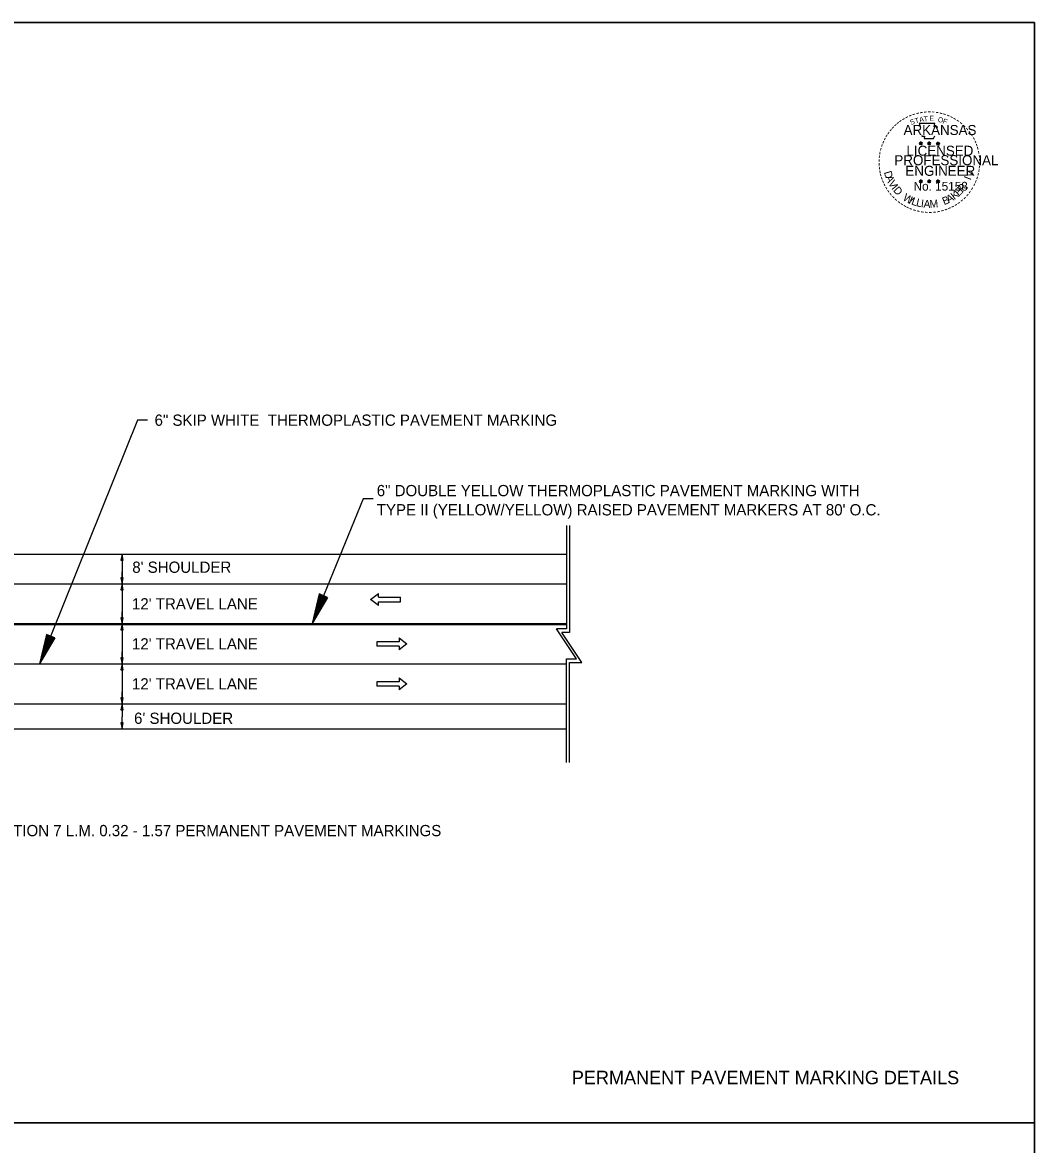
# Model space of a CAD drawing. Extents: x 1373096 to 1373266, y 381130 to 381790.
# Drawn here: x 1373164.8 to 1373266, y 381568 to 381680.2 of the extents above; entities that cross this region are included whole.
import ezdxf

# ---------------------------------------------------------------- set-up
doc = ezdxf.new("R2010")
doc.units = 0
for name, color, linetype in [('Default', 7, 'Continuous'), ('DSN_DRFT_Junk-No-Plot', 7, 'Continuous'), ('R_Border Notes', 7, 'Continuous'), ('R_Border PE', 7, 'Continuous'), ('R_Draft', 7, 'Continuous')]:
    doc.layers.add(name, color=color, linetype=linetype)

msp = doc.modelspace()

# ---------------------------------------------------------------- linework, layer by layer
at = {"layer": 'Default'}
for p, q in [((1373176.29, 381640.41), (1373166.5, 381616.04)), ((1373177.29, 381640.41), (1373176.29, 381640.41)), ((1373198.85, 381632.56), (1373193.75, 381620.09)), ((1373199.85, 381632.56), (1373198.85, 381632.56)), ((1373219.17, 381629.87), (1373219.17, 381619.54)), ((1373219.5, 381629.87), (1373219.5, 381619.2)), ((1373194.46, 381623.04), (1373193.75, 381620.09)), ((1373195.29, 381622.7), (1373193.75, 381620.09)), ((1373194.53, 381623.01), (1373193.94, 381620.55)), ((1373195.22, 381622.73), (1373193.94, 381620.55)), ((1373194.6, 381622.98), (1373194.13, 381621.03)), ((1373195.15, 381622.76), (1373194.13, 381621.03)), ((1373194.67, 381622.96), (1373194.32, 381621.5)), ((1373195.08, 381622.79), (1373194.32, 381621.5)), ((1373195.29, 381622.7), (1373194.46, 381623.04)), ((1373194.74, 381622.93), (1373194.51, 381621.97)), ((1373195.01, 381622.82), (1373194.51, 381621.97)), ((1373194.81, 381622.9), (1373194.7, 381622.43)), ((1373194.94, 381622.85), (1373194.7, 381622.43)), ((1373199.6, 381622.49), (1373200.38, 381623.09)), ((1373200.38, 381621.89), (1373199.6, 381622.49)), ((1373200.38, 381622.71), (1373200.38, 381623.09)), ((1373200.38, 381622.71), (1373202.58, 381622.71)), ((1373202.58, 381622.26), (1373202.58, 381622.71)), ((1373200.38, 381622.26), (1373202.58, 381622.26)), ((1373200.38, 381621.89), (1373200.38, 381622.26)), ((1373219.17, 381619.54), (1373218.17, 381619.54)), ((1373220.17, 381616.54), (1373218.17, 381619.54)), ((1373220.72, 381616.2), (1373218.72, 381619.2)), ((1373219.5, 381619.2), (1373218.72, 381619.2)), ((1373167.2, 381618.99), (1373166.5, 381616.04)), ((1373168.04, 381618.65), (1373166.5, 381616.04)), ((1373167.27, 381618.96), (1373166.69, 381616.5)), ((1373167.97, 381618.68), (1373166.69, 381616.5)), ((1373167.34, 381618.93), (1373166.88, 381616.98)), ((1373167.9, 381618.71), (1373166.88, 381616.98)), ((1373167.41, 381618.9), (1373167.07, 381617.44)), ((1373167.83, 381618.74), (1373167.07, 381617.44)), ((1373168.04, 381618.65), (1373167.2, 381618.99)), ((1373167.48, 381618.88), (1373167.26, 381617.92)), ((1373167.75, 381618.77), (1373167.26, 381617.92)), ((1373167.55, 381618.85), (1373167.44, 381618.38)), ((1373167.68, 381618.79), (1373167.44, 381618.38)), ((1373202.45, 381618.26), (1373200.24, 381618.26)), ((1373200.24, 381618.26), (1373200.24, 381617.81)), ((1373202.45, 381618.64), (1373202.45, 381618.26)), ((1373202.45, 381618.64), (1373203.23, 381618.04)), ((1373203.23, 381618.04), (1373202.45, 381617.44)), ((1373202.45, 381617.81), (1373200.24, 381617.81)), ((1373202.45, 381617.81), (1373202.45, 381617.44)), ((1373219.17, 381606.2), (1373219.17, 381616.54)), ((1373219.17, 381616.54), (1373220.17, 381616.54)), ((1373219.5, 381606.2), (1373219.5, 381616.2)), ((1373219.5, 381616.2), (1373220.72, 381616.2)), ((1373202.45, 381614.64), (1373202.45, 381614.26)), ((1373202.45, 381614.64), (1373203.23, 381614.04)), ((1373202.45, 381614.26), (1373200.24, 381614.26)), ((1373200.24, 381614.26), (1373200.24, 381613.81)), ((1373202.45, 381613.81), (1373200.24, 381613.81)), ((1373203.23, 381614.04), (1373202.45, 381613.44)), ((1373202.45, 381613.81), (1373202.45, 381613.44))]:
    msp.add_line(p, q, dxfattribs=at)
for points in [[(1373095.97, 381680.17), (1373095.97, 381570.17), (1373265.97, 381570.17), (1373265.97, 381680.17)], [(1373095.97, 381680.17), (1373095.97, 381570.17), (1373265.97, 381570.17), (1373265.97, 381680.17)], [(1373095.97, 381570.17), (1373095.97, 381460.17), (1373265.97, 381460.17), (1373265.97, 381570.17)]]:
    msp.add_lwpolyline(points, close=True, dxfattribs=at)
at = {"layer": 'DSN_DRFT_Junk-No-Plot'}
msp.add_line((1373174.76, 381625.81), (1373174.76, 381610.74), dxfattribs=at)
for points in [[(1373095.97, 381680.17), (1373265.97, 381680.17), (1373265.97, 381570.17), (1373095.97, 381570.17)], [(1373095.97, 381680.17), (1373095.97, 381570.17), (1373265.97, 381570.17), (1373265.97, 381680.17)], [(1373095.97, 381570.17), (1373265.97, 381570.17), (1373265.97, 381460.17), (1373095.97, 381460.17)], [(1373095.97, 381570.17), (1373095.97, 381460.17), (1373265.97, 381460.17), (1373265.97, 381570.17)]]:
    msp.add_lwpolyline(points, close=True, dxfattribs=at)
for points in [[(1373174.76, 381627.01), (1373174.64, 381626.41), (1373174.88, 381626.41), (1373174.76, 381627.01), (1373174.76, 381625.81)], [(1373174.76, 381624.04), (1373174.88, 381624.64), (1373174.64, 381624.64), (1373174.76, 381624.04), (1373174.76, 381625.24)], [(1373174.76, 381624.04), (1373174.88, 381624.64), (1373174.64, 381624.64), (1373174.76, 381624.04), (1373174.76, 381625.24)], [(1373174.76, 381624.04), (1373174.64, 381623.44), (1373174.88, 381623.44), (1373174.76, 381624.04), (1373174.76, 381622.84)], [(1373174.76, 381620.04), (1373174.88, 381620.64), (1373174.64, 381620.64), (1373174.76, 381620.04), (1373174.76, 381621.24)], [(1373174.76, 381620.04), (1373174.64, 381619.44), (1373174.88, 381619.44), (1373174.76, 381620.04), (1373174.76, 381618.84)], [(1373174.76, 381616.04), (1373174.88, 381616.64), (1373174.64, 381616.64), (1373174.76, 381616.04), (1373174.76, 381617.24)], [(1373174.76, 381616.04), (1373174.64, 381615.44), (1373174.88, 381615.44), (1373174.76, 381616.04), (1373174.76, 381614.84)], [(1373174.76, 381612.04), (1373174.88, 381612.64), (1373174.64, 381612.64), (1373174.76, 381612.04), (1373174.76, 381613.24)], [(1373174.76, 381612.04), (1373174.64, 381611.44), (1373174.88, 381611.44), (1373174.76, 381612.04), (1373174.76, 381610.84)], [(1373174.76, 381609.54), (1373174.88, 381610.14), (1373174.64, 381610.14), (1373174.76, 381609.54), (1373174.76, 381610.74)]]:
    msp.add_lwpolyline(points, dxfattribs=at)
at = {"layer": 'R_Border PE'}
for p, q in [((1373254.43, 381668.13), (1373254.6, 381668.07)), ((1373254.43, 381668.13), (1373254.56, 381668.11)), ((1373254.43, 381668.13), (1373254.55, 381668.07)), ((1373254.5, 381667.93), (1373254.6, 381668.07)), ((1373254.5, 381667.93), (1373254.56, 381668.05)), ((1373254.5, 381667.93), (1373254.6, 381668.03)), ((1373254.6, 381668.26), (1373254.58, 381668.13)), ((1373254.6, 381668.07), (1373254.6, 381668.26)), ((1373254.6, 381668.26), (1373254.63, 381668.13)), ((1373254.78, 381668.13), (1373254.6, 381668.07)), ((1373254.71, 381667.93), (1373254.6, 381668.07)), ((1373254.71, 381667.93), (1373254.6, 381668.03)), ((1373254.78, 381668.13), (1373254.63, 381668.11)), ((1373254.71, 381667.93), (1373254.64, 381668.07)), ((1373254.78, 381668.13), (1373254.67, 381668.08)), ((1373255.26, 381668.13), (1373255.44, 381668.07)), ((1373255.26, 381668.13), (1373255.39, 381668.11)), ((1373255.26, 381668.13), (1373255.38, 381668.07)), ((1373255.33, 381667.93), (1373255.44, 381668.07)), ((1373255.33, 381667.93), (1373255.39, 381668.05)), ((1373255.33, 381667.93), (1373255.44, 381668.03)), ((1373255.44, 381668.26), (1373255.42, 381668.13)), ((1373255.44, 381668.07), (1373255.44, 381668.26)), ((1373255.44, 381668.26), (1373255.46, 381668.13)), ((1373255.61, 381668.13), (1373255.44, 381668.07)), ((1373255.54, 381667.93), (1373255.44, 381668.07)), ((1373255.54, 381667.93), (1373255.44, 381668.03)), ((1373255.61, 381668.13), (1373255.47, 381668.11)), ((1373255.54, 381667.93), (1373255.48, 381668.07)), ((1373255.61, 381668.13), (1373255.51, 381668.08)), ((1373256.15, 381668.12), (1373256.32, 381668.07)), ((1373256.15, 381668.12), (1373256.27, 381668.1)), ((1373256.15, 381668.12), (1373256.26, 381668.06)), ((1373256.21, 381667.92), (1373256.32, 381668.07)), ((1373256.21, 381667.92), (1373256.28, 381668.04)), ((1373256.21, 381667.92), (1373256.32, 381668.03)), ((1373256.32, 381668.25), (1373256.3, 381668.12)), ((1373256.32, 381668.07), (1373256.32, 381668.25)), ((1373256.32, 381668.25), (1373256.34, 381668.13)), ((1373256.49, 381668.12), (1373256.32, 381668.07)), ((1373256.43, 381667.92), (1373256.32, 381668.07)), ((1373256.43, 381667.92), (1373256.32, 381668.03)), ((1373256.49, 381668.12), (1373256.35, 381668.1)), ((1373256.43, 381667.92), (1373256.36, 381668.07)), ((1373256.49, 381668.12), (1373256.39, 381668.07)), ((1373254.43, 381664.34), (1373254.6, 381664.29)), ((1373254.43, 381664.34), (1373254.55, 381664.32)), ((1373254.43, 381664.34), (1373254.55, 381664.28)), ((1373254.49, 381664.14), (1373254.6, 381664.29)), ((1373254.49, 381664.14), (1373254.56, 381664.26)), ((1373254.49, 381664.14), (1373254.6, 381664.25)), ((1373254.6, 381664.47), (1373254.58, 381664.34)), ((1373254.6, 381664.29), (1373254.6, 381664.47)), ((1373254.6, 381664.47), (1373254.63, 381664.35)), ((1373254.77, 381664.34), (1373254.6, 381664.29)), ((1373254.71, 381664.14), (1373254.6, 381664.29)), ((1373254.71, 381664.14), (1373254.6, 381664.25)), ((1373254.77, 381664.34), (1373254.63, 381664.32)), ((1373254.71, 381664.14), (1373254.64, 381664.28)), ((1373254.77, 381664.34), (1373254.67, 381664.29)), ((1373255.26, 381664.34), (1373255.44, 381664.29)), ((1373255.26, 381664.34), (1373255.39, 381664.32)), ((1373255.26, 381664.34), (1373255.38, 381664.28)), ((1373255.33, 381664.14), (1373255.44, 381664.29)), ((1373255.33, 381664.14), (1373255.39, 381664.26)), ((1373255.33, 381664.14), (1373255.43, 381664.25)), ((1373255.44, 381664.47), (1373255.42, 381664.34)), ((1373255.54, 381664.14), (1373255.43, 381664.25)), ((1373255.44, 381664.29), (1373255.44, 381664.47)), ((1373255.44, 381664.47), (1373255.46, 381664.35)), ((1373255.61, 381664.34), (1373255.44, 381664.29)), ((1373255.54, 381664.14), (1373255.44, 381664.29)), ((1373255.61, 381664.34), (1373255.47, 381664.32)), ((1373255.54, 381664.14), (1373255.47, 381664.28)), ((1373255.61, 381664.34), (1373255.51, 381664.29)), ((1373256.14, 381664.34), (1373256.32, 381664.28)), ((1373256.14, 381664.34), (1373256.27, 381664.32)), ((1373256.14, 381664.34), (1373256.26, 381664.28)), ((1373256.21, 381664.13), (1373256.32, 381664.28)), ((1373256.21, 381664.13), (1373256.27, 381664.26)), ((1373256.21, 381664.13), (1373256.32, 381664.24)), ((1373256.32, 381664.47), (1373256.3, 381664.34)), ((1373256.32, 381664.28), (1373256.32, 381664.47)), ((1373256.32, 381664.47), (1373256.34, 381664.34)), ((1373256.49, 381664.34), (1373256.32, 381664.28)), ((1373256.43, 381664.13), (1373256.32, 381664.28)), ((1373256.43, 381664.13), (1373256.32, 381664.24)), ((1373256.49, 381664.34), (1373256.35, 381664.31)), ((1373256.43, 381664.13), (1373256.36, 381664.28)), ((1373256.49, 381664.34), (1373256.39, 381664.29))]:
    msp.add_line(p, q, dxfattribs=at)
for points in [[(1373254.45, 381670.07), (1373254.58, 381669.66)], [(1373256.2, 381669.61), (1373256.28, 381669.75), (1373255.93, 381669.74), (1373256.01, 381670.07), (1373254.45, 381670.07)], [(1373254.7, 381668.86), (1373254.7, 381668.81), (1373254.98, 381668.8), (1373254.95, 381668.57), (1373255.88, 381668.57), (1373255.99, 381668.84)], [(1373254.6, 381668.26), (1373254.71, 381667.93), (1373254.43, 381668.13), (1373254.78, 381668.13), (1373254.5, 381667.93), (1373254.6, 381668.26)], [(1373255.44, 381668.26), (1373255.54, 381667.93), (1373255.26, 381668.13), (1373255.61, 381668.13), (1373255.33, 381667.93), (1373255.44, 381668.26)], [(1373256.32, 381668.25), (1373256.43, 381667.92), (1373256.15, 381668.12), (1373256.49, 381668.12), (1373256.21, 381667.92), (1373256.32, 381668.25)], [(1373254.6, 381664.47), (1373254.71, 381664.14), (1373254.43, 381664.34), (1373254.77, 381664.34), (1373254.49, 381664.14), (1373254.6, 381664.47)], [(1373255.44, 381664.47), (1373255.54, 381664.14), (1373255.26, 381664.34), (1373255.61, 381664.34), (1373255.33, 381664.14), (1373255.44, 381664.47)], [(1373256.32, 381664.47), (1373256.43, 381664.13), (1373256.14, 381664.34), (1373256.49, 381664.34), (1373256.21, 381664.13), (1373256.32, 381664.47)]]:
    msp.add_lwpolyline(points, dxfattribs=at)
for centre, radius in [((1373254.6, 381668.07), 0.0861), ((1373254.6, 381668.07), 0.0723), ((1373254.6, 381668.07), 0.0579), ((1373254.6, 381668.07), 0.0495), ((1373254.6, 381668.07), 0.0374), ((1373254.6, 381668.07), 0.0248), ((1373254.6, 381668.07), 0.0148), ((1373255.44, 381668.07), 0.0861), ((1373255.44, 381668.07), 0.0723), ((1373255.44, 381668.07), 0.0579), ((1373255.44, 381668.07), 0.0495), ((1373255.44, 381668.07), 0.0374), ((1373255.44, 381668.07), 0.0248), ((1373255.44, 381668.07), 0.0148), ((1373256.32, 381668.07), 0.0861), ((1373256.32, 381668.07), 0.0723), ((1373256.32, 381668.07), 0.0579), ((1373256.32, 381668.07), 0.0495), ((1373256.32, 381668.07), 0.0374), ((1373256.32, 381668.07), 0.0248), ((1373256.32, 381668.07), 0.0148), ((1373254.6, 381664.29), 0.0861), ((1373254.6, 381664.29), 0.0723), ((1373254.6, 381664.29), 0.0579), ((1373254.6, 381664.29), 0.0495), ((1373254.6, 381664.29), 0.0374), ((1373254.6, 381664.29), 0.0248), ((1373254.6, 381664.29), 0.0148), ((1373255.44, 381664.29), 0.0861), ((1373255.44, 381664.29), 0.0723), ((1373255.44, 381664.29), 0.0579), ((1373255.44, 381664.29), 0.0495), ((1373255.44, 381664.29), 0.0374), ((1373255.44, 381664.29), 0.0248), ((1373255.44, 381664.29), 0.0148), ((1373256.32, 381664.28), 0.0861), ((1373256.32, 381664.28), 0.0723), ((1373256.32, 381664.28), 0.0579), ((1373256.32, 381664.28), 0.0495), ((1373256.32, 381664.28), 0.0374), ((1373256.32, 381664.28), 0.0248), ((1373256.32, 381664.28), 0.0148)]:
    msp.add_circle(centre, radius, dxfattribs=at)
at = {"layer": 'R_Draft'}
for p, q in [((1373142.77, 381627.01), (1373219.16, 381627.01)), ((1373142.78, 381624.04), (1373219.17, 381624.04)), ((1373142.78, 381624.04), (1373219.17, 381624.04)), ((1373142.74, 381620.09), (1373219.14, 381620.09)), ((1373142.81, 381619.99), (1373219.2, 381619.99)), ((1373142.78, 381616.04), (1373219.17, 381616.04)), ((1373142.78, 381612.04), (1373219.17, 381612.04)), ((1373142.74, 381609.54), (1373219.13, 381609.54))]:
    msp.add_line(p, q, dxfattribs=at)

# ---------------------------------------------------------------- texts
at = {"layer": 'Default'}
for s, p in [('6" SKIP WHITE  THERMOPLASTIC PAVEMENT MARKING', (1373178.01, 381639.85)), ('6" DOUBLE YELLOW THERMOPLASTIC PAVEMENT MARKING WITH ', (1373200.22, 381632.81)), ("TYPE II (YELLOW/YELLOW) RAISED PAVEMENT MARKERS AT 80' O.C.", (1373200.22, 381630.89)), ("8' SHOULDER", (1373175.78, 381625.15)), ("12' TRAVEL LANE", (1373175.75, 381621.49)), ("12' TRAVEL LANE", (1373175.75, 381617.49)), ("12' TRAVEL LANE", (1373175.75, 381613.49)), ("6' SHOULDER", (1373175.96, 381610.05))]:
    msp.add_text(s, height=1.125, dxfattribs=at).set_placement(p)
at = {"layer": 'R_Border Notes'}
msp.add_text('PERMANENT PAVEMENT MARKING DETAILS', height=1.35, dxfattribs=at).set_placement((1373219.72, 381574.02))
at = {"layer": 'R_Border PE'}
for s, height, rotation, p in [('-', 0.8, 28.7918, (1373253.19, 381670.34)), ('-', 0.8, 24.3072, (1373253.51, 381670.5)), ('-', 0.8, 19.1761, (1373253.82, 381670.63)), ('T', 0.5, 16.4036, (1373254.08, 381670.07)), ('-', 0.8, 13.6302, (1373254.2, 381670.75)), ('A', 0.5, 11.2132, (1373254.5, 381670.2)), ('-', 0.8, 10.2193, (1373254.54, 381670.83)), ('T', 0.5, 6.0228, (1373254.92, 381670.28)), ('-', 0.8, 5.8968, (1373254.9, 381670.89)), ('-', 0.8, 0.1862, (1373255.29, 381670.92)), ('E', 0.5, 0.8323, (1373255.47, 381670.34)), ('-', 0.8, 357.743, (1373255.65, 381670.92)), ('-', 0.8, 352.1617, (1373256.02, 381670.89)), ('O', 0.5, 350.4515, (1373256.28, 381670.23)), ('-', 0.8, 347.2049, (1373256.38, 381670.83)), ('-', 0.8, 342.3362, (1373256.7, 381670.76)), ('-', 0.8, 337.8551, (1373257.07, 381670.64)), ('-', 0.8, 334.1211, (1373257.38, 381670.51)), ('-', 0.8, 329.6409, (1373257.67, 381670.37)), ('-', 0.8, 50.6142, (1373251.72, 381669.08)), ('-', 0.8, 48.4231, (1373251.92, 381669.32)), ('-', 0.8, 42.9622, (1373252.15, 381669.56)), ('-', 0.8, 38.9507, (1373252.36, 381669.77)), ('-', 0.8, 36.2317, (1373252.6, 381669.96)), ('-', 0.8, 34.0636, (1373252.89, 381670.15)), ('S', 0.5, 21.594, (1373253.63, 381669.91)), ('F', 0.5, 340.0707, (1373256.75, 381670.12)), ('-', 0.8, 325.8627, (1373257.99, 381670.19)), ('-', 0.8, 320.5297, (1373258.3, 381669.97)), ('-', 0.8, 315.5786, (1373258.6, 381669.73)), ('-', 0.8, 309.8797, (1373258.88, 381669.45)), ('-', 0.8, 62.8713, (1373251.2, 381668.22)), ('-', 0.8, 58.0706, (1373251.35, 381668.53)), ('-', 0.8, 54.2325, (1373251.52, 381668.79)), ('-', 0.8, 306.6522, (1373259.14, 381669.15)), ('-', 0.7, 303.6753, (1373259.39, 381668.87)), ('-', 0.8, 299.6684, (1373259.55, 381668.57)), ('-', 0.8, 75.461, (1373250.86, 381667.25)), ('-', 0.8, 72.3945, (1373250.96, 381667.6)), ('-', 0.8, 67.7743, (1373251.07, 381667.92)), ('-', 0.8, 294.6628, (1373259.71, 381668.26)), ('-', 0.8, 290.5728, (1373259.84, 381667.97)), ('-', 0.8, 285.1233, (1373259.95, 381667.68)), ('-', 0.8, 280.5493, (1373260.05, 381667.31)), ('-', 0.8, 89.0622, (1373250.74, 381666.19)), ('-', 0.8, 85.1863, (1373250.75, 381666.54)), ('-', 0.8, 81.2013, (1373250.79, 381666.89)), ('-', 0.8, 276.5962, (1373260.13, 381666.93)), ('-', 0.8, 274.3301, (1373260.16, 381666.57)), ('-', 0.8, 269.9407, (1373260.18, 381666.25)), ('-', 0.8, 94.1959, (1373250.76, 381665.83)), ('-', 0.8, 98.9479, (1373250.8, 381665.5)), ('-', 0.8, 101.7149, (1373250.86, 381665.13)), ('-', 0.8, 105.4578, (1373250.94, 381664.83)), ('D', 0.77, 286.2848, (1373250.91, 381665.2)), ('V', 0.77, 72.6573, (1373259.7, 381664.62)), ('-', 0.8, 255.7626, (1373260.08, 381665.25)), ('-', 0.8, 260.9953, (1373260.14, 381665.59)), ('-', 0.8, 263.5172, (1373260.17, 381665.92)), ('-', 0.8, 109.0874, (1373251.05, 381664.52)), ('-', 0.8, 114.0643, (1373251.18, 381664.22)), ('-', 0.8, 115.7289, (1373251.33, 381663.91)), ('A', 0.77, 292.7835, (1373251.05, 381664.7)), ('V', 0.77, 300.7936, (1373251.31, 381664.11)), ('I', 0.77, 308.3502, (1373251.63, 381663.59)), ('R', 0.77, 50.3651, (1373258.77, 381663.11)), ('I', 0.77, 69.0301, (1373259.59, 381664.35)), ('-', 0.8, 244.6197, (1373259.75, 381664.24)), ('-', 0.8, 247.8887, (1373259.88, 381664.55)), ('-', 0.8, 252.8681, (1373259.99, 381664.89)), ('-', 0.8, 120.4471, (1373251.51, 381663.62)), ('-', 0.8, 125.8934, (1373251.71, 381663.34)), ('-', 0.8, 130.7181, (1373251.94, 381663.06)), ('-', 0.8, 134.2238, (1373252.2, 381662.79)), ('D', 0.77, 311.9774, (1373251.8, 381663.36)), ('W', 0.77, 328.0731, (1373252.74, 381662.47)), ('B', 0.77, 22.8589, (1373256.94, 381661.9)), ('A', 0.77, 28.9042, (1373257.39, 381662.09)), ('K', 0.77, 36.9143, (1373257.95, 381662.41)), ('E', 0.77, 44.0175, (1373258.4, 381662.75)), (',', 0.77, 57.4684, (1373259.13, 381663.55)), ('-', 0.8, 231.2538, (1373259.14, 381663.25)), ('-', 0.8, 233.8452, (1373259.35, 381663.54)), ('-', 0.8, 239.0712, (1373259.55, 381663.86)), ('-', 0.8, 138.9338, (1373252.46, 381662.56)), ('-', 0.8, 144.6463, (1373252.74, 381662.35)), ('-', 0.8, 148.0898, (1373253.02, 381662.17)), ('-', 0.8, 151.5704, (1373253.31, 381662.01)), ('-', 0.8, 154.6002, (1373253.57, 381661.88)), ('I', 0.77, 336.6877, (1373253.33, 381662.12)), ('L', 0.77, 340.3149, (1373253.6, 381662)), ('L', 0.77, 346.6625, (1373254.08, 381661.83)), ('I', 0.77, 353.0101, (1373254.58, 381661.71)), ('A', 0.77, 356.6373, (1373254.86, 381661.66)), ('M', 0.77, 4.6473, (1373255.51, 381661.64)), ('-', 0.8, 204.2516, (1373257.5, 381661.96)), ('-', 0.8, 207.3568, (1373257.81, 381662.12)), ('-', 0.8, 212.2491, (1373258.09, 381662.29)), ('-', 0.8, 215.7363, (1373258.36, 381662.48)), ('-', 0.8, 221.0851, (1373258.63, 381662.72)), ('-', 0.8, 225.7653, (1373258.9, 381662.97)), ('-', 0.8, 158.5612, (1373253.88, 381661.76)), ('-', 0.8, 162.7983, (1373254.23, 381661.65)), ('-', 0.8, 167.5555, (1373254.59, 381661.57)), ('-', 0.8, 173.1155, (1373254.97, 381661.51)), ('-', 0.8, 176.5183, (1373255.35, 381661.49)), ('-', 0.8, 181.5918, (1373255.72, 381661.49)), ('-', 0.8, 185.8167, (1373256.12, 381661.53)), ('-', 0.8, 191.2858, (1373256.49, 381661.6)), ('-', 0.8, 195.4743, (1373256.85, 381661.7)), ('-', 0.8, 199.4643, (1373257.19, 381661.82))]:
    msp.add_text(s, height=height, rotation=rotation, dxfattribs=at).set_placement(p)
for s, height, p in [('ARKANSAS', 1, (1373252.88, 381668.92)), ('LICENSED', 1, (1373253.17, 381666.85)), ('PROFESSIONAL', 1, (1373251.96, 381665.9)), ('ENGINEER', 1, (1373253.06, 381664.84)), ('No. 15158', 0.878, (1373253.88, 381663.36)), ('AAMU', 0.00001, (1373255.4, 381661.63))]:
    msp.add_text(s, height=height, dxfattribs=at).set_placement(p)
at = {"layer": 'R_Draft'}
msp.add_text('HWY. 65 SECTION 7 L.M. 0.32 - 1.57 PERMANENT PAVEMENT MARKINGS', height=1.125, dxfattribs=at).set_placement((1373154.34, 381598.82))

doc.saveas('drawing.dxf')
